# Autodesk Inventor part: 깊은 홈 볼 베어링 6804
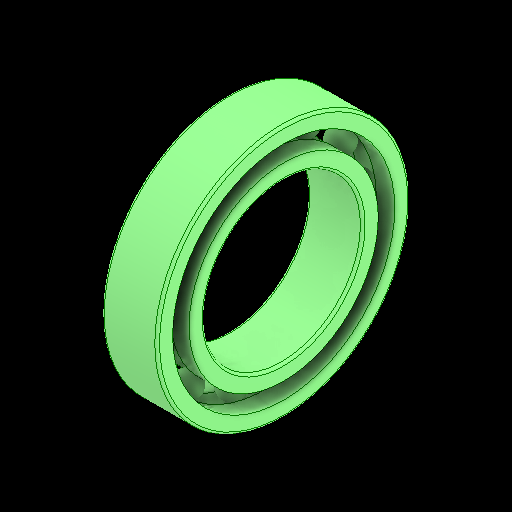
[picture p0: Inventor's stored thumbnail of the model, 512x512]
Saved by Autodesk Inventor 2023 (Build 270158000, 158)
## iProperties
Created: 2025-01
Part Number: 깊은 홈 볼 베어링 6804
Material: 강철, 연강
Description: 깊은 그루부 볼 베어링
Document SubType Name: Modeling
Designer: 강의실01
Density: 7.85 g/cm^3
Appearance: 기본값
Author: jhkim
Sending System: Autodesk Inventor 2025
Preprocessor: ST-DEVELOPER v20
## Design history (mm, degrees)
feature "Solid1"
feature "Solid1:1"
feature "Solid1:2"
feature "Solid1:3"
feature "Solid1:4"
feature "Solid1:5"
feature "Solid1:6"
feature "Solid1:7"
feature "Solid1:8"
feature "Solid1:9"
feature "Solid1:10"
feature "Solid1:11"
feature "Solid1:12"
feature "Solid1:13"
feature "Solid1:14"
node "솔리드1"
node "솔리드2"
node "솔리드3"
node "솔리드4"
node "솔리드5"
node "솔리드6"
node "솔리드7"
node "솔리드8"
node "솔리드9"
node "솔리드10"
node "솔리드11"
node "솔리드12"
node "솔리드13"
node "솔리드14"
node "솔리드15"
